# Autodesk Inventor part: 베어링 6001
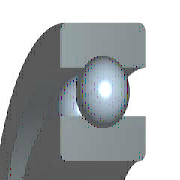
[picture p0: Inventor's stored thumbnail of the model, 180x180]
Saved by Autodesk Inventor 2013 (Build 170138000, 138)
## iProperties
IsCustomPart: 0
Created: 2015-10
Part Number: 베어링 6001
Material: 강, 연강
Description: 깊은 그루브 볼 베어링
Document SubType Name: Modeling
Standard: KS B 2023
Designer: mdu
Standards Organization: KS
Language: ko-KR
Size Designation: 6001 - 12 x 28 x 8
Categories: <MemberInstance><Categories><Category DisplayName="샤프트 부품" InternalName="7f7aeb1f-a693-4053-b835-cee3144e0d98" Mnemonic="SHFT"><Category DisplayName="베어링" Inter
Density: 1 g/cm^3
Author: mdu
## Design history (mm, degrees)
sketch "스케치" dims "d0" = 4.16 (= -0.26 x WD + 0.26 x BD)
  geometry: L1 (1.92, 10)-(6.08, 10); L2 (4, 10)-(4, 7.92); L3 (4, 10)-(4, 12.08); L4 (2.454, 8.608)-(0, 8.608); L5 (0, 6)-(8, 6); L6 (2.454, 11.392)-(0, 11.392); L7 (0, 14)-(8, 14); L8 (8, 6)-(8, 8.608); L9 (5.546, 8.608)-(8, 8.608); L10 (5.546, 11.392)-(8, 11.392); L11 (8, 14)-(8, 11.392); L12 (-1.4, 0)-(8.4, 0) reference; L13 (0, -0.3)-(0, 5.3) reference
  constraints: 22 end point, 4 point on line, 2 collinear, 2 perpendicular, 2 symmetric about line, 1 midpoint, 1 parallel, 14 other
  dimensions: "d9" = 12 diameter of L5 L12 (= WD); "d11" = 28 diameter of L7 L12 (= BD); "d12" = 8 distance between parallel lines of L8 L13 (= KB); "d13" = 17.216 diameter of L9 L12 (= 0.326 x BD + 0.674 x WD)
revolve "본체" stored, may be unused: angle "d6" = 90 deg
revolve "볼" stored, may be unused: angle "d7" = 90 deg
pattern_circular "IDS_ARRAYBALL[SIMPL:T]" dims angle "d3" = 360 deg
body "Solid1"
fillet "모깎기1" dims "d1" = 0.3 (= KRS)
other parameters: "WD" = 12 [user parameter; used in 5 equation terms], "BD" = 28 [user parameter; used in 5 equation terms], "KB" = 8 [user parameter; used in 1 equation term], "KRS" = 0.3 [user parameter; used in 1 equation term], "d4" = 0, "d5" = 0, "d8" = 0, "d14" = 0, "d15" = 0, "BBA" = 0 [user parameter], "BC0" = 2360000 [user parameter], "BC" = 5070000 [user parameter], "BR" = 14 (= 0.5 x BD) [user parameter], "WR" = 6 (= 0.5 x WD) [user parameter]
